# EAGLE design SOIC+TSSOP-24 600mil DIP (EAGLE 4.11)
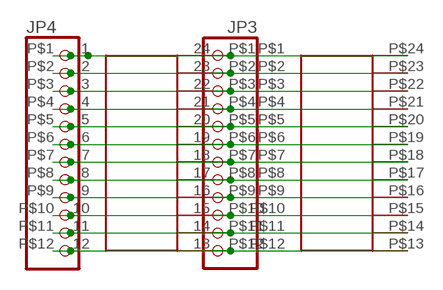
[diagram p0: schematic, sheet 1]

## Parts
JP3  PINHD-1X12THIN  [HEADER1X12]
JP4  PINHD-1X12THIN  [HEADER1X12]
U$1  SMD-24SOIC  [SO-24NMW]
U$2  SMD-24TSSOP  [TSSOP-24NM]

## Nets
N$1: JP3.P$1 U$1.P$1 U$2.24
N$2: JP3.P$2 U$1.P$2 U$2.23
N$3: JP3.P$3 U$1.P$3 U$2.22
N$4: JP3.P$4 U$1.P$4 U$2.21
N$5: JP3.P$5 U$1.P$5 U$2.20
N$6: JP3.P$6 U$1.P$6 U$2.19
N$7: JP3.P$7 U$1.P$7 U$2.18
N$8: JP3.P$8 U$1.P$8 U$2.17
N$9: JP3.P$9 U$1.P$9 U$2.16
N$10: JP3.P$10 U$1.P$10 U$2.15
N$11: JP3.P$11 U$1.P$11 U$2.14
N$12: JP3.P$12 U$1.P$12 U$2.13
N$13: JP4.P$1 U$1.P$24 U$2.1
N$14: JP4.P$2 U$1.P$23 U$2.2
N$15: JP4.P$3 U$1.P$22 U$2.3
N$16: JP4.P$4 U$1.P$21 U$2.4
N$17: JP4.P$5 U$1.P$20 U$2.5
N$18: JP4.P$6 U$1.P$19 U$2.6
N$19: JP4.P$7 U$1.P$18 U$2.7
N$20: JP4.P$8 U$1.P$17 U$2.8
N$21: JP4.P$9 U$1.P$16 U$2.9
N$22: JP4.P$10 U$1.P$15 U$2.10
N$23: JP4.P$11 U$1.P$14 U$2.11
N$24: JP4.P$12 U$1.P$13 U$2.12

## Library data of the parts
JP3 JP4 = boogie:PINHD-1X12: PIN HEADER
U$1 U$2 = boogie:SMD-24

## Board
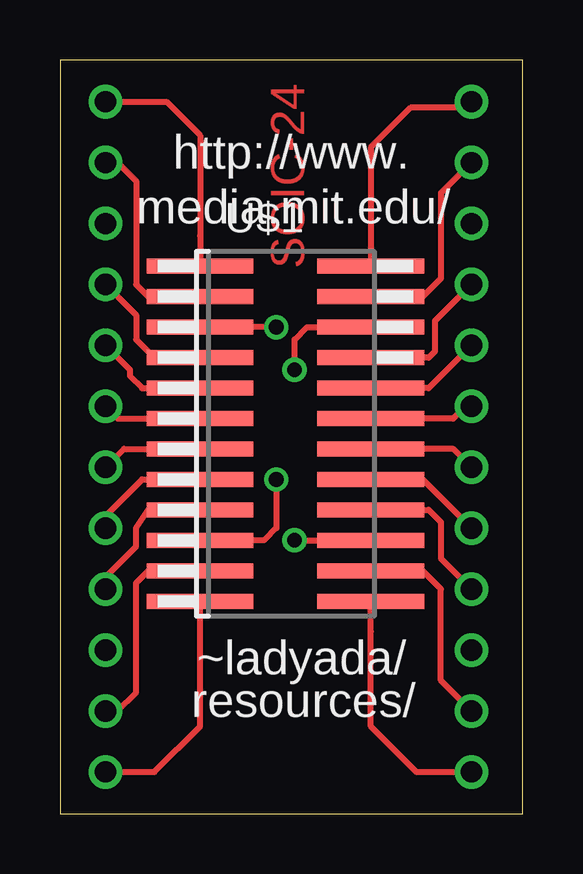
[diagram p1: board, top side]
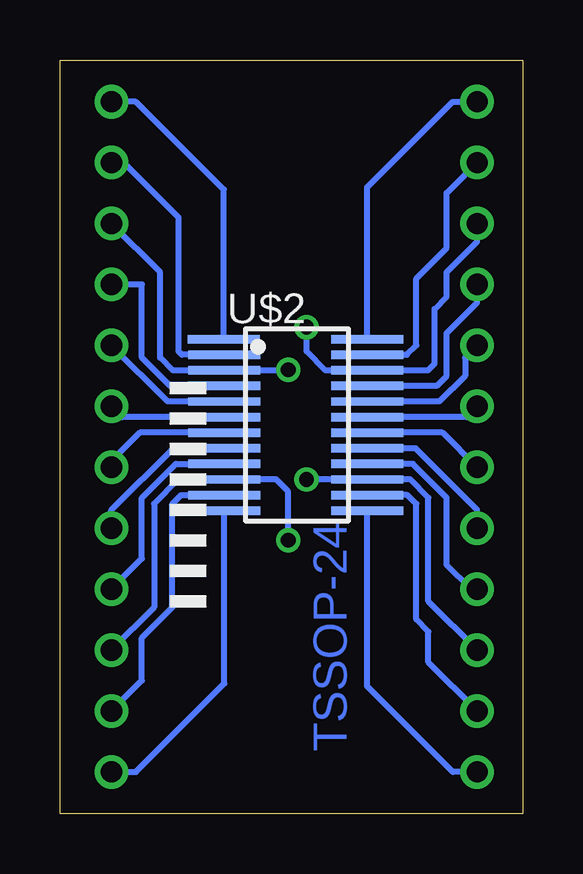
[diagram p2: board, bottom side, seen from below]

Size 19.28 x 31.42 mm. Coordinates in mm from the lower left corner, seen from the top.
Outline: 0,0 19.28,0 19.28,31.42 0,31.42 0,0
Copper layers (1*16): Top 0.035mm / dielectric 1.5mm / Bottom 0.035mm
Design rules "default": minimum track width 10mil, minimum drill 24mil, track to track 10mil, track to pad 10mil, pad to pad 10mil, via to via 10mil, smd to smd 10mil, copper to edge 40mil, drill to drill 8mil, minimum pad ring 10mil, minimum via ring 8mil, stop-mask expansion 4mil, vias tented up to drill 0mil, thermal gap 10mil

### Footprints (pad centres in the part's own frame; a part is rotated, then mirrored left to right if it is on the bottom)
HEADER1X12 = drill 0.889 round: P$1 12.7,0; P$2 10.16,0; P$3 7.62,0; P$4 5.08,0; P$5 2.54,0; P$6 0,0; P$7 -2.54,0; P$8 -5.08,0; P$9 -7.62,0; P$10 -10.16,0; P$11 -12.7,0; P$12 -15.24,0
SO-24NMW = smd 0.635 x 4.445: P$1 -4.572,-3.683; P$2 -3.302,-3.683; P$3 -2.032,-3.683; P$4 -0.762,-3.683; P$5 0.508,-3.683; P$6 1.778,-3.683; P$7 3.048,-3.683; P$8 4.318,-3.683; P$9 5.588,-3.683; P$10 6.858,-3.683; P$11 8.128,-3.683; P$12 9.398,-3.683; P$13 9.398,3.429; P$14 8.128,3.429; P$15 6.858,3.429; P$16 5.588,3.429; P$17 4.318,3.429; P$18 3.048,3.429; P$19 1.778,3.429; P$20 0.508,3.429; P$21 -0.762,3.429; P$22 -2.032,3.429; P$23 -3.302,3.429; P$24 -4.572,3.429
TSSOP-24NM = smd 0.35 x 3: 1 -3.045,-3.193; 2 -2.405,-3.169; 3 -1.755,-3.169; 4 -1.105,-3.169; 5 -0.455,-3.169; 6 0.195,-3.169; 7 0.845,-3.169; 8 1.495,-3.169; 9 2.145,-3.169; 10 2.795,-3.169; 11 3.445,-3.169; 12 4.095,-3.169; 13 4.095,2.781; 14 3.445,2.781; 15 2.795,2.781; 16 2.145,2.781; 17 1.495,2.781; 18 0.845,2.781; 19 0.195,2.781; 20 -0.455,2.781; 21 -1.105,2.781; 22 -1.755,2.781; 23 -2.405,2.781; 24 -3.055,2.781

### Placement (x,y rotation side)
JP3  1.9,16.98 90 top
JP4  17.14,16.98 90 top
U$1  9.52,18.25 270 top
U$2  9.27,16.73 270 bottom

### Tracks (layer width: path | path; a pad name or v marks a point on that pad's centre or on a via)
N$1
  Top 0.254: U$1.P$1 5.84,24.09 5.84,28.28 4.44,29.68 JP3.P$1
  Bottom 0.254: U$2.24 6.49,26.11 2.92,29.68 JP3.P$1
N$2
  Top 0.254: U$1.P$2 3.68,21.55 3.17,22.06 3.17,26.38 2.41,27.14 JP3.P$2
  Bottom 0.254: U$2.23 4.83,19.13 4.44,19.52 4.44,22.31 3.17,23.58 3.17,25.87 JP3.P$2
N$3  (via drill 0.61)
  Top 0.254: v9.01,20.28 U$1.P$3
  Bottom 0.254: JP3.P$3 1.9,23.84 3.17,22.57 3.17,21.55 3.68,21.04 3.68,18.76 3.95,18.48 U$2.22 8.23,18.48 9.01,19.27 v9.01,20.28
N$4
  Top 0.254: U$1.P$4 3.93,19.01 3.17,19.77 3.17,20.79 JP3.P$4
  Bottom 0.254: U$2.21 3.59,17.83 3.17,18.25 3.17,20.03 1.9,21.3 JP3.P$4
N$5
  Top 0.254: U$1.P$5 3.42,17.74 2.92,18.25 2.92,18.5 JP3.P$5
  Bottom 0.254: U$2.20 3.48,17.18 2.41,18.25 2.41,19.01 JP3.P$5
N$6
  Top 0.254: U$1.P$6 2.41,16.47 JP3.P$6
  Bottom 0.254: U$2.19 2.35,16.53 JP3.P$6
N$7
  Top 0.254: U$1.P$7 2.66,15.2 JP3.P$7
  Bottom 0.254: U$2.18 3.34,15.88 JP3.P$7
N$8
  Top 0.254: U$1.P$8 3.42,13.93 1.9,12.41 JP3.P$8
  Bottom 0.254: U$2.17 4.47,15.23 1.9,12.66 JP3.P$8
N$9
  Top 0.254: U$1.P$9 3.68,12.66 3.17,11.9 3.17,11.14 1.9,9.87 JP3.P$9
  Bottom 0.254: U$2.16 4.58,14.58 3.17,13.17 3.17,10.38 2.15,9.36 JP3.P$9
N$10  (via drill 0.61)
  Top 0.254: U$1.P$10 8.5,11.39 9.01,11.9 v9.01,13.93
  Bottom 0.254: JP3.P$10 3.93,8.85 3.93,13.17 4.69,13.93 U$2.15 v9.01,13.93
N$11
  Top 0.254: U$1.P$11 3.68,10.12 3.17,9.61 3.17,5.04 2.41,4.28 JP3.P$11
  Bottom 0.254: U$2.14 4.81,13.28 4.44,12.92 4.44,8.09 3.93,7.58 3.93,6.31 JP3.P$11
N$12
  Top 0.254: U$1.P$12 5.84,7.07 5.84,3.65 3.93,1.74 JP3.P$12
  Bottom 0.254: U$2.13 6.49,5.31 2.92,1.74 JP3.P$12
N$13
  Top 0.254: U$1.P$24 12.95,24.35 12.95,27.77 14.6,29.43 17.14,29.43 JP4.P$1
  Bottom 0.254: U$2.1 12.46,26.02 16.12,29.68 JP4.P$1
N$14
  Top 0.254: U$1.P$23 15.11,21.55 15.87,22.31 15.87,25.87 JP4.P$2
  Bottom 0.254: U$2.2 14.21,19.13 14.35,19.27 14.35,24.85 16.63,27.14 JP4.P$2
N$15  (via drill 0.61)
  Top 0.254: v9.77,18.5 9.77,19.77 10.28,20.28 U$1.P$22 13.08,20.28
  Bottom 0.254: JP4.P$3 15.11,22.57 15.11,19.01 14.58,18.48 U$2.3 9.8,18.48 v9.77,18.5
N$16
  Top 0.254: U$1.P$21 15.36,19.01 15.62,19.27 15.62,20.54 JP4.P$4
  Bottom 0.254: U$2.4 14.69,17.83 15.87,19.01 15.87,22.06 JP4.P$4
N$17
  Top 0.254: U$1.P$20 15.36,17.74 JP4.P$5
  Bottom 0.254: U$2.5 14.8,17.18 JP4.P$5
N$18
  Top 0.254: JP4.P$6 16.89,16.98 16.38,16.47 U$1.P$19
  Bottom 0.254: U$2.6 16.69,16.53 JP4.P$6
N$19
  Top 0.254: U$1.P$18 16.38,15.2 JP4.P$7
  Bottom 0.254: U$2.7 15.95,15.88 17.14,14.69 JP4.P$7
N$20
  Top 0.254: U$1.P$17 15.11,13.93 JP4.P$8
  Bottom 0.254: U$2.8 14.57,15.23 17.14,12.66 JP4.P$8
N$21
  Top 0.254: U$1.P$16 15.36,12.66 15.87,12.15 15.87,10.63 JP4.P$9
  Bottom 0.254: U$2.9 14.46,14.58 15.87,13.17 15.87,10.63 JP4.P$9
N$22  (via drill 0.61)
  Top 0.254: v9.77,11.39 U$1.P$15
  Bottom 0.254: 12.57,13.93 14.35,13.93 15.36,12.92 15.36,8.6 JP4.P$10 | 12.57,13.93 U$2.10 | v9.77,11.39 9.77,13.42 10.28,13.93 12.57,13.93
N$23
  Top 0.254: U$1.P$14 15.11,10.12 15.87,9.36 15.87,5.55 JP4.P$11
  Bottom 0.254: U$2.11 14.23,13.28 14.6,12.92 14.6,8.6 15.87,7.33 15.87,5.55 JP4.P$11
N$24
  Top 0.254: U$1.P$13 12.95,7.58 12.95,3.65 14.85,1.74 JP4.P$12
  Bottom 0.254: U$2.12 12.43,5.43 16.12,1.74 JP4.P$12

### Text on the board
Top: SOIC-24
Bottom: TSSOP-24
tPlace: http://www. | media.mit.edu/ | ~ladyada/ | resources/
